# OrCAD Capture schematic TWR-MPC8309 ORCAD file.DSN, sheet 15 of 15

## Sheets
15 P12:CF, 1588, JTAG & I2C Device: size C; title: ColdFire MCU, IEEE1588, JTAG and I2C Device
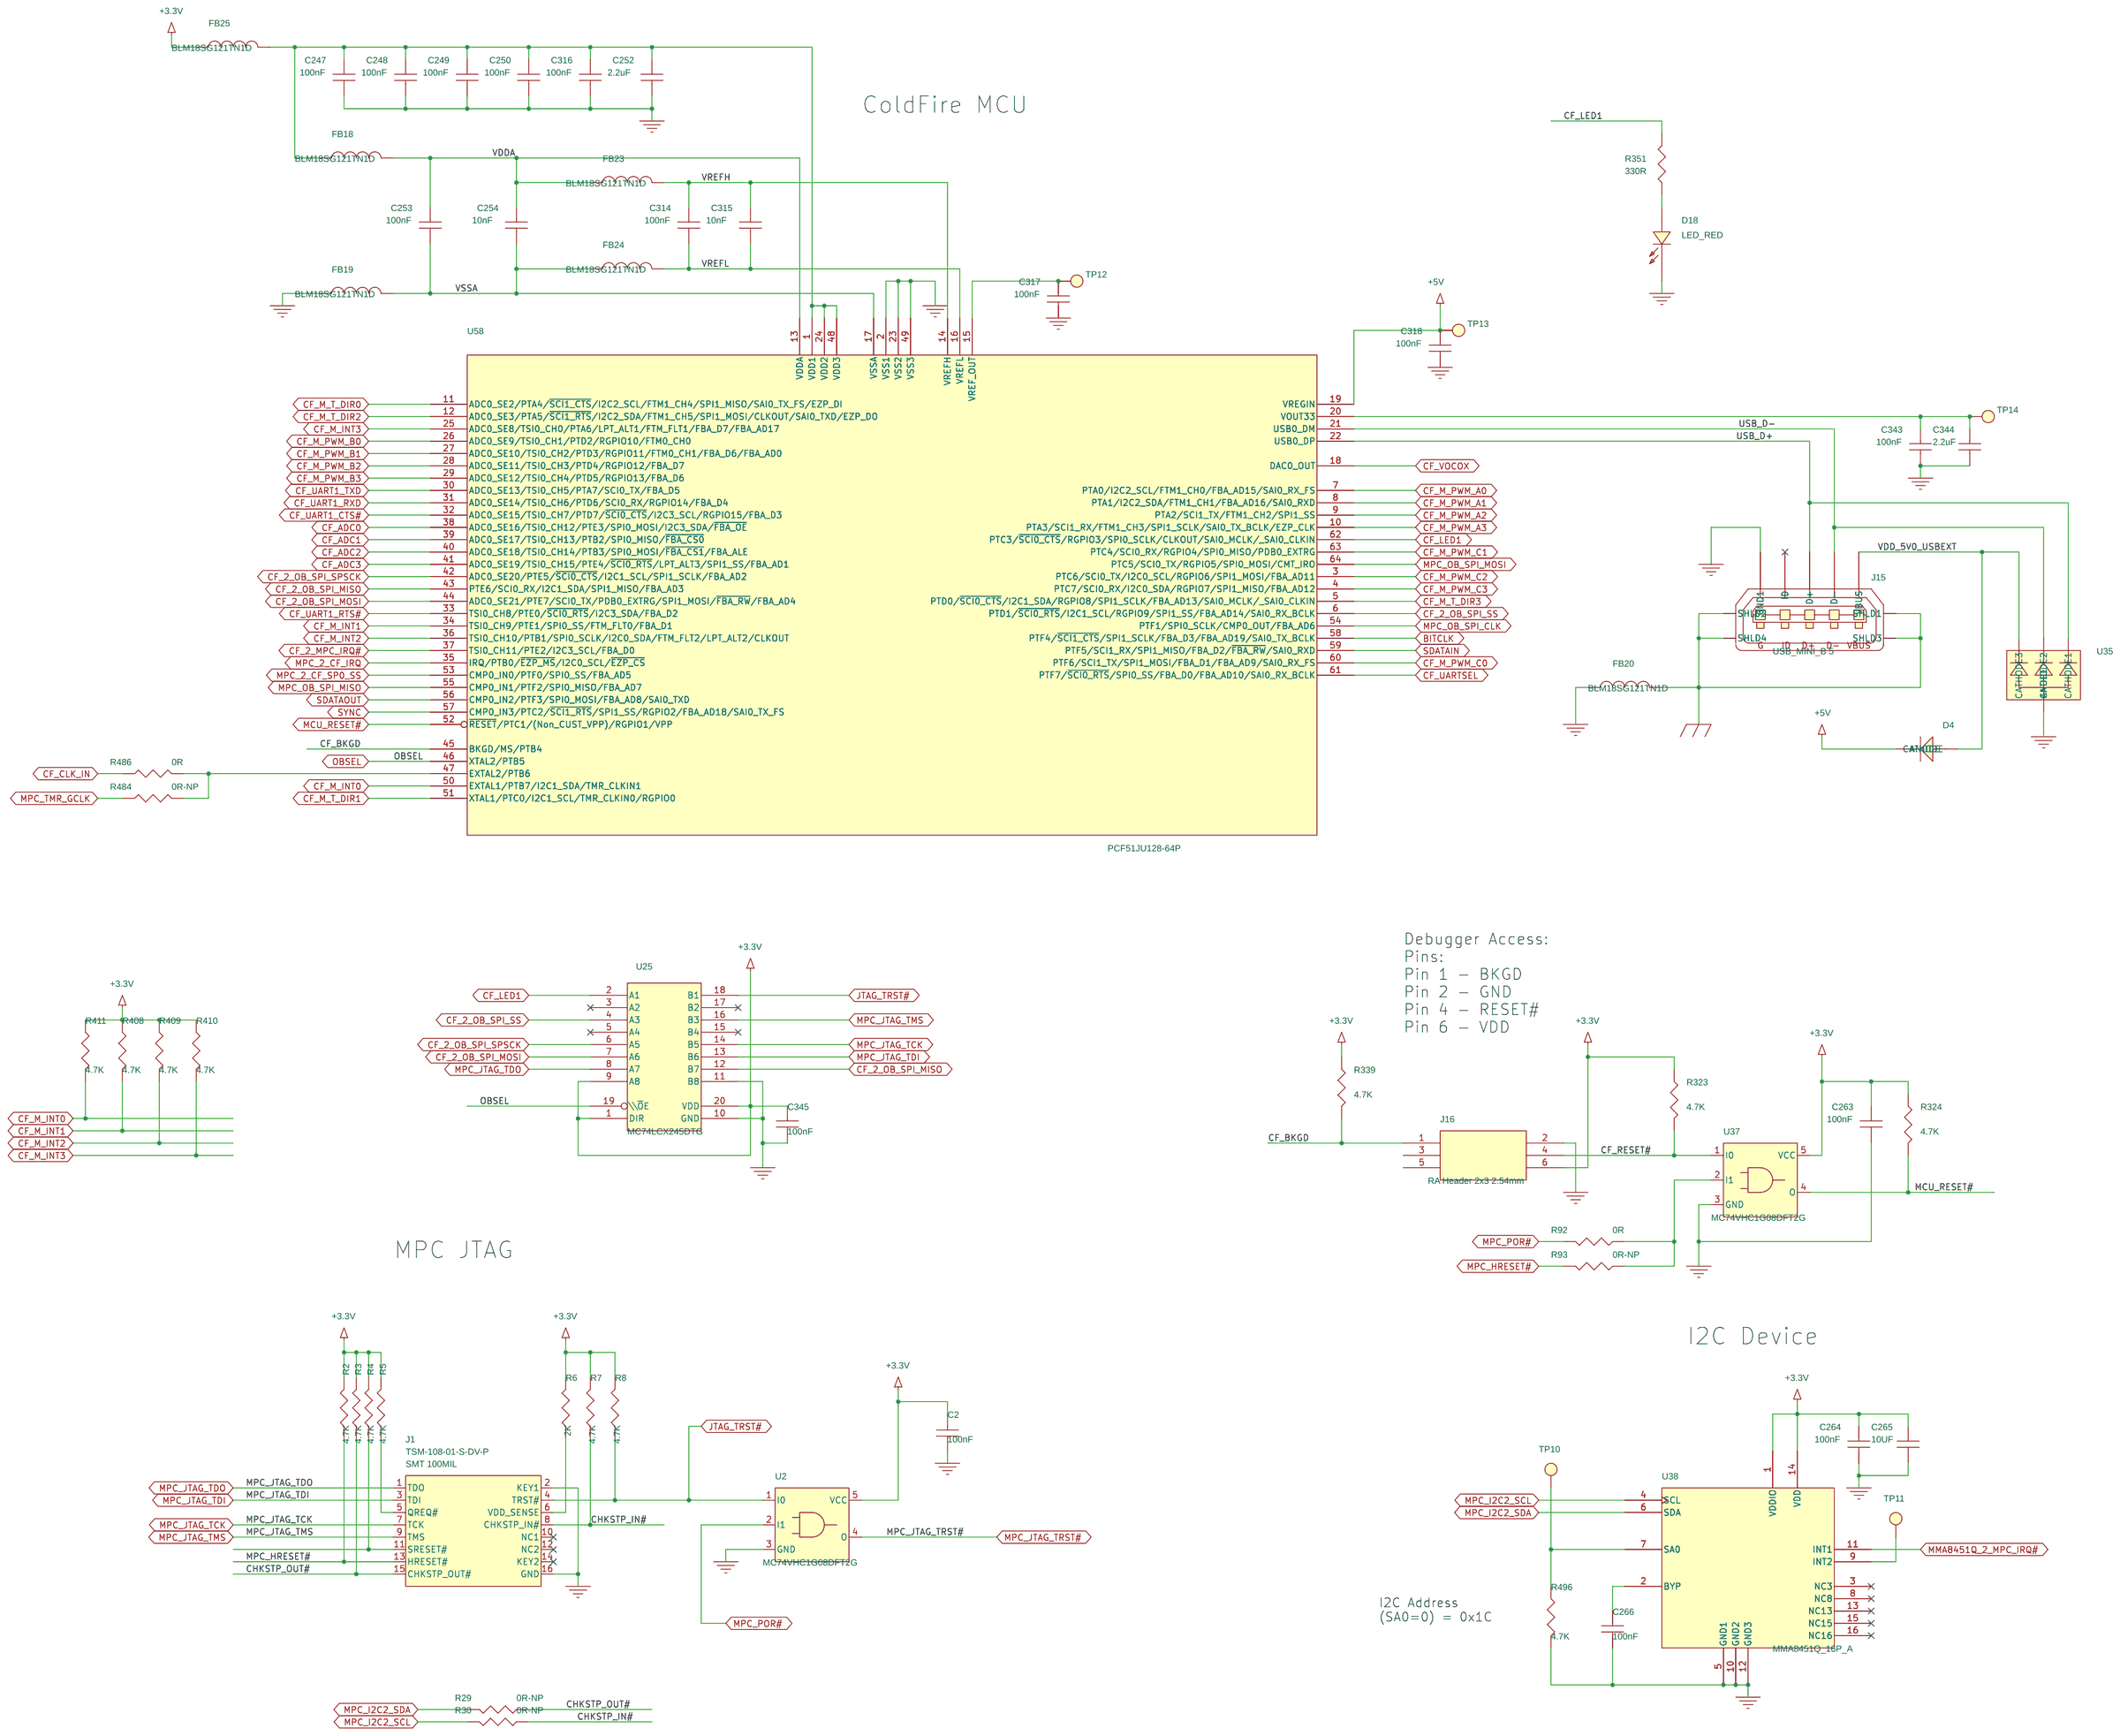
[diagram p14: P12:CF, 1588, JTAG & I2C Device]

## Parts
C2  100nF  [CC0402_CR]
C247  100nF  [CC0402_CR]
C248  100nF  [CC0402_CR]
C249  100nF  [CC0402_CR]
C250  100nF  [CC0402_CR]
C252  2.2uF  [CC0603]
C253  100nF  [CC0402_CR]
C254  10nF  [CC0402_CR]
C263  100nF  [CC0402_CR]
C264  100nF  [CC0402_CR]
C265  10UF  [CC0805]
C266  100nF  [CC0402_CR]
C314  100nF  [CC0402_CR]
C315  10nF  [CC0402_CR]
C316  100nF  [CC0402_CR]
C317  100nF  [CC0402_CR]
C318  100nF  [CC0402_CR]
C343  100nF  [CC0402_CR]
C344  2.2uF  [CC0603]
C345  100nF  [CC0402_CR]
D4  RB060M_30  [SOD_123]
D18  LED_RED  [LED0603]
FB18  BLM18SG121TN1D  [L0603]
FB19  BLM18SG121TN1D  [L0603]
FB20  BLM18SG121TN1D  [L0603]
FB23  BLM18SG121TN1D  [L0603]
FB24  BLM18SG121TN1D  [L0603]
FB25  BLM18SG121TN1D  [L0603]
J1  TSM-108-01-S-DV-P  [Header100_SMD2X8]
J15  USB_MINI_B 5  [CON5_MUSB_ABC_0P8_RA_SMT]
J16  RA Header 2x3 2.54mm  [header100_smd2x3_ra]
R2  4.7K  [R0402_CR]
R3  4.7K  [R0402_CR]
R4  4.7K  [R0402_CR]
R5  4.7K  [R0402_CR]
R6  2K  [R0402_CR]
R7  4.7K  [R0402_CR]
R8  4.7K  [R0402_CR]
R29  0R-NP  [R0402_CR]
R30  0R-NP  [R0402_CR]
R92  0R  [R0402_CR]
R93  0R-NP  [R0402_CR]
R323  4.7K  [R0402_CR]
R324  4.7K  [R0402_CR]
R339  4.7K  [R0402_CR]
R351  330R  [R0402_CR]
R408  4.7K  [R0402_CR]
R409  4.7K  [R0402_CR]
R410  4.7K  [R0402_CR]
R411  4.7K  [R0402_CR]
R484  0R-NP  [R0402_CR]
R486  0R  [R0402_CR]
R496  4.7K  [R0402_CR]
TP10  TP  [SMD_TP]
TP11  TP  [SMD_TP]
TP12  TP  [SMD_TP]
TP13  TP  [SMD_TP]
TP14  TP  [SMD_TP]
U2  MC74VHC1G08DFT2G  [SOT353]
U25  MC74LCX245DTG  [TSSOP20A]
U35  SP0503B  [sot143]
U37  MC74VHC1G08DFT2G  [SOT353]
U38  MMA8451Q_16P_A  [qfn16_0p5_3p03x3p03]
U58  PCF51JU128-64P  [LQFP64_0P5_10x10]

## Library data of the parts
C2 = CAP_NP: Mfg: Kemet; Mfg Part#: C0402C104K8PACTU; Oper. Temp. Range: -55°C ~ 85°C; Package: 0402; Price @ 100 pcs: 0.014; Price @ 10K: 0.0060; Price @ 1K: 0.0066; RoHS Compliant?: Yes; Specifications: CAP .10UF 10V CERAMIC X5R 0402; Vendor: Digikey; Vendor Part#: 399-3027-1-ND
C247-C250 C252-C254 C263 C264 C266 C314-C318 C343 C345 = CAP_NP: CAP CER 0.1UF 16V 10% X7R 0402; AGILE_PN: 150-75182; CAD_APPROVED: Yes; FPLIST: CC0402_25,CC0402_HD,0402_CC; HEIGHT: 0.635MM; MFG_NAME01: MURATA; MFG_PN01: GRM155R71C104KA88D; ROHS: Yes; ROOM: OSBDM; Tolerance: 10%
C265 C344 = CAP_NP: CAP CER 10UF 6.3V 10% X5R 0603; AGILE_PN: 150-77832; CAD_APPROVED: Yes; FPLIST: CC0603_OV,CC0603,0603_CC; HEIGHT: 1.0MM; MFG_NAME01: CAL-CHIP; MFG_PN01: GMC10X5R106K6R3NTLF; ROHS: Yes; ROOM: OSBDM; Tolerance: 10%
D4 = DIODE_0: DIODE PWR RECT 2A 600V 403A-03; AGILE_PN: 480-77641; CAD_APPROVED: Yes; HEIGHT: 2.45MM; MFG_NAME01: ON SEMICONDUCTOR; MFG_PN01: MURS060T3G; ROHS: Yes; ROOM: POWER
D18 = LED: Mfg: Lumex; Mfg Part#: SML-LX0603GW-TR; Package: 0603; RoHS Compliant?: Yes; Specifications: LED 565NM GRN DIFF 0603 SMD
FB18 FB19 FB23-FB25 = INDUCTOR_0: Ferrite Bead, 2A, 140 OHMS, 1GHZ, SMD0603; Cost_Proto: 0.25; Cost_Vol: 0.14; Mfg: Murata; Mfg Part No: BLM18EG101TN1; Room: OSBDM
FB20 = Bead: Ferrite Bead, 6000mA, 0.007E, SMD, 0603; Mfg: Murata; Mfg Part No: BLM18SG260TN1D; Part Number: GBX-R-00000033; ROOM: USB
J1 = CONN_16Pin_2x8_MPC_JTAG: Mfg: Samtec; Oper. Temp. Range: -40°C ~ 105°C; Package: SMT 100MIL; Price @ 100 pcs: 1.4; Price @ 10K: 0.918; Price @ 1K: 1.19; RoHS Compliant?: Yes; Specifications: HDR 2X8 SMT PLUG 100MIL SP 380H AU; Vendor: Samtec
J15 = USB_MINI_B_SKT: CON 1X5 USB MINI-B RA SHLD SKT SMT 0.8MM SP 159H AU; AGILE_PN: 211-78723; CAD_APPROVED: Yes; HEIGHT: 4.05MM; MFG_NAME01: WIN WIN PRECISION INDUSTRIAL CO. LTD; MFG_PN01: MUBF-5S-TSROBTC; ROHS: Yes; ROOM: OSBDM
J16 = Conn_BDC_2x3_male_Header_0: Mfg: Samtec; Mfg Part#: TSM-103-01-L-DV; Package: SMD 100mil; Price @ 100 pcs: 0.324; Price @ 10K: 0.268; Price @ 1K: 0.324; RoHS Compliant?: Yes; Specifications: Conn Header 100mil x 100mil SMD; Vendor: Samtec; Vendor Part#: TSM-103-01-L-DV
R2-R5 = RESISTOR: Mfg: Yageo; Mfg Part#: RC0402JR-075K1L; Oper. Temp. Range: -55°C ~ 85°C; Package: 0402; Price @ 100 pcs: 0.066; Price @ 10K: 0.002; Price @ 1K: 0.035; RoHS Compliant?: Yes; Specifications: RES 5.1K OHM 1/16W 5% 0402 SMD; Vendor: Digikey; Vendor Part#: 311-5.1KJRCT-ND
R6 = RESISTOR: Mfg: Yageo; Mfg Part#: RC0402JR-072KL; Oper. Temp. Range: -55°C ~ 85°C; Package: 0402; Price @ 100 pcs: 0.035; Price @ 10K: 0.002; Price @ 1K: 0.0138; RoHS Compliant?: Yes; Specifications: RES 2.0K OHM 1/16W 5% 0402 SMD; Vendor: Digikey; Vendor Part#: RC0402JR-072KL
R7 R29 R30 R92 R93 = RESISTOR: Mfg: Yageo; Mfg Part#: RC0402JR-074K7L; Oper. Temp. Range: -55°C ~ 85°C; Package: 0402; Price @ 100 pcs: 0.0066; Price @ 10K: 0.00213; Price @ 1K: 0.035; RoHS Compliant?: Yes; Specifications: RES 4.7K OHM 1/16W 5% 0402 SMD; Vendor: Digikey; Vendor Part#: 311-4.7KJRCT-ND
R8 = RESISTOR: Mfg: Yageo; Mfg Part#: RC0402JR-0710KL; Oper. Temp. Range: -55°C ~ 85°C; Package: 0402; Price @ 100 pcs: 0.066; Price @ 10K: 0.00213; Price @ 1K: 0.035; RoHS Compliant?: Yes; Specifications: RES 10K OHM 1/16W 5% 0402 SMD; Vendor: Digikey; Vendor Part#: 311-10KJRCT-ND
R323 R324 R339 R408-R411 R496 = Res: Res, 4.7K, 5%, Chip, 0.063W, SMD, Size 0402; GDA Part No: GRX-R-00000587; Mfg: KOA; Mfg Part No: RK73B1ETTP472J; Part Number: GRX-R-00000587; ROOM: OSBDM; Sub_Type: Chip; Tolerance: 5%
R351 = Res: Res, 100K, 1%, Chip, 0.063W, SMD, Size 0402; FPLIST: R0402; GDA Part No: GRX-R-00000037; Mfg: KOA; Mfg Part No: RK73H1ETTP1003F; Part Number: GRX-R-00000037; ROOM: POWER; Sub_Type: Chip; Tolerance: 1%
R484 R486 = RESISTOR: Mfg: Yageo; Mfg Part#: RC0402FR-0722RL; Package: 0402; Price @ 100 pcs: 0.066; Price @ 10K: 0.036; Price @ 1K: 0.00243; RoHS Compliant?: Yes; Specifications: RES 22.0 OHM 1/16W 1% 0402 SMD; Vendor: Digikey; Vendor Part#: 311-22.0LRCT-ND
TP10 TP11 = TP: RoHS Compliant?: Yes
TP12-TP14 = TP
U2 U37 = 74VHC1G08: IC GATE AND SGL 2-INPUT 2-5.5V SOT-353; AGILE_PN: 312-79604; CAD_APPROVED: Yes; CLASS: IC; HEIGHT: 1.1MM; MFG_NAME01: ON SEMICONDUCTOR; MFG_PN01: MC74VHC1G08DFT1G; ROHS: Yes
U25 = 74LCX245: CLASS: IC
U35 = SPB0503: DIODE TVS ARRAY 3CH -- 5V 0.225W SOT143; AGILE_PN: 480-76886; CAD_APPROVED: Yes; HEIGHT: 1.22MM; MFG_NAME01: LITTELFUSE; MFG_PN01: SP0503BAHTG; ROHS: Yes; ROOM: OSBDM
U38 = MMA8451Q_16P_A
U58 = PCF51JU128-64P

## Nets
+3.3V: C2.2 C263.1 C264.1 C265.1 C345.1 FB25.2 J16.6 R2.2 R3.2 R4.2 R5.2 R6.2 R7.2 R8.2 R323.2 R324.2 R339.2 R408.2 R409.2 R410.2 R411.2 U2.5(VCC) U25.1(DIR) U25.9(A8) U25.20(VDD) U37.5(VCC) U38.1(VDDIO) U38.14(VDD) ; also on sheet 1 2 4 5 7 8 9 10 11 12 13 14
+5V: C318.1 D4.2(ANODE) TP13.1(TP) U58.19(VREGIN) ; also on sheet 1 5 9 11 12
GND: C2.1 C247.2 C248.2 C249.2 C250.2 C252.2 C263.2 C264.2 C265.2 C266.2 C316.2 C317.2 C318.2 C343.2 C344.2 C345.2 D18.2(CATHODE) FB19.2 FB20.2 J1.2(KEY1) J1.16(GND) J15.5(GND1) J16.2 R496.1 U2.3(GND) U25.10(GND) U25.11(B8) U35.1(ANODE) U37.3(GND) U38.5(GND1) U38.10(GND2) U38.12(GND3) U58.2(VSS1) U58.23(VSS2) U58.49(VSS3) ; also on sheet 1 2 4 5 6 7 8 9 10 11 12 13 14
GND_EARTH1: FB20.1 J15.S1(SHLD1) J15.S2(SHLD2) J15.S3(SHLD3) J15.S4(SHLD4)
VDD_5V0_USBEXT: D4.1(CATHODE) J15.1(VBUS) U35.4(CATHODE3)
VDDA: C253.1 C254.1 FB18.1 FB23.2 U58.13(VDDA)
VSSA: C253.2 C254.2 FB19.1 FB24.2 U58.17(VSSA)
BITCLK: U58.58(PTF4/~{SCI1_CTS}/SPI1_SCLK/FBA_D3/FBA_AD19/SAI0_TX_BCLK) ; also on sheet 2
CF_2_MPC_IRQ#: U58.37(TSI0_CH11/PTE2/I2C3_SCL/FBA_D0) ; also on sheet 13
CF_2_OB_SPI_MISO: U25.12(B7) U58.43(PTE6/SCI0_RX/I2C1_SDA/SPI1_MISO/FBA_AD3) ; also on sheet 6
CF_2_OB_SPI_MOSI: U25.7(A6) U58.44(ADC0_SE21/PTE7/SCI0_TX/PDB0_EXTRG/SPI1_MOSI/~{FBA_RW}/FBA_AD4) ; also on sheet 6
CF_2_OB_SPI_SPSCK: U25.6(A5) U58.42(ADC0_SE20/PTE5/~{SCI0_CTS}/I2C1_SCL/SPI1_SCLK/FBA_AD2) ; also on sheet 6
CF_2_OB_SPI_SS: U25.4(A3) U58.6(PTD1/~{SCI0_RTS}/I2C1_SCL/RGPIO9/SPI1_SS/FBA_AD14/SAI0_RX_BCLK) ; also on sheet 6
CF_ADC0: U58.38(ADC0_SE16/TSI0_CH12/PTE3/SPI0_MOSI/I2C3_SDA/~{FBA_OE}) ; also on sheet 5 6
CF_ADC1: U58.39(ADC0_SE17/TSI0_CH13/PTB2/SPI0_MISO/~{FBA_CS0}) ; also on sheet 5 6
CF_ADC2: U58.40(ADC0_SE18/TSI0_CH14/PTB3/SPI0_MOSI/~{FBA_CS1}/FBA_ALE) ; also on sheet 5 6
CF_ADC3: U58.41(ADC0_SE19/TSI0_CH15/PTE4/~{SCI0_RTS}/LPT_ALT3/SPI1_SS/FBA_AD1) ; also on sheet 5 6
CF_BKGD: J16.1 R339.1 U58.45(BKGD/MS/PTB4)
CF_CLK_IN: R486.1 ; also on sheet 8
CF_LED1: R351.2 U25.2(A1) U58.62(PTC3/~{SCI0_CTS}/RGPIO3/SPI0_SCLK/CLKOUT/SAI0_MCLK/_SAI0_CLKIN)
CF_M_INT0: R411.1 U58.50(EXTAL1/PTB7/I2C1_SDA/TMR_CLKIN1) ; also on sheet 6
CF_M_INT1: R408.1 U58.34(TSI0_CH9/PTE1/SPI0_SS/FTM_FLT0/FBA_D1) ; also on sheet 6
CF_M_INT2: R409.1 U58.36(TSI0_CH10/PTB1/SPI0_SCLK/I2C0_SDA/FTM_FLT2/LPT_ALT2/CLKOUT) ; also on sheet 6
CF_M_INT3: R410.1 U58.25(ADC0_SE8/TSI0_CH0/PTA6/LPT_ALT1/FTM_FLT1/FBA_D7/FBA_AD17) ; also on sheet 6
CF_M_PWM_A0: U58.7(PTA0/I2C2_SCL/FTM1_CH0/FBA_AD15/SAI0_RX_FS) ; also on sheet 6
CF_M_PWM_A1: U58.8(PTA1/I2C2_SDA/FTM1_CH1/FBA_AD16/SAI0_RXD) ; also on sheet 6
CF_M_PWM_A2: U58.9(PTA2/SCI1_TX/FTM1_CH2/SPI1_SS) ; also on sheet 6
CF_M_PWM_A3: U58.10(PTA3/SCI1_RX/FTM1_CH3/SPI1_SCLK/SAI0_TX_BCLK/EZP_CLK) ; also on sheet 6
CF_M_PWM_B0: U58.26(ADC0_SE9/TSI0_CH1/PTD2/RGPIO10/FTM0_CH0) ; also on sheet 6
CF_M_PWM_B1: U58.27(ADC0_SE10/TSI0_CH2/PTD3/RGPIO11/FTM0_CH1/FBA_D6/FBA_AD0) ; also on sheet 6
CF_M_PWM_B2: U58.28(ADC0_SE11/TSI0_CH3/PTD4/RGPIO12/FBA_D7) ; also on sheet 6
CF_M_PWM_B3: U58.29(ADC0_SE12/TSI0_CH4/PTD5/RGPIO13/FBA_D6) ; also on sheet 6
CF_M_PWM_C0: U58.60(PTF6/SCI1_TX/SPI1_MOSI/FBA_D1/FBA_AD9/SAI0_RX_FS) ; also on sheet 6
CF_M_PWM_C1: U58.63(PTC4/SCI0_RX/RGPIO4/SPI0_MISO/PDB0_EXTRG) ; also on sheet 6
CF_M_PWM_C2: U58.3(PTC6/SCI0_TX/I2C0_SCL/RGPIO6/SPI1_MOSI/FBA_AD11) ; also on sheet 6
CF_M_PWM_C3: U58.4(PTC7/SCI0_RX/I2C0_SDA/RGPIO7/SPI1_MISO/FBA_AD12) ; also on sheet 6
CF_M_T_DIR0: U58.11(ADC0_SE2/PTA4/~{SCI1_CTS}/I2C2_SCL/FTM1_CH4/SPI1_MISO/SAI0_TX_FS/EZP_DI) ; also on sheet 6
CF_M_T_DIR1: U58.51(XTAL1/PTC0/I2C1_SCL/TMR_CLKIN0/RGPIO0) ; also on sheet 6
CF_M_T_DIR2: U58.12(ADC0_SE3/PTA5/~{SCI1_RTS}/I2C2_SDA/FTM1_CH5/SPI1_MOSI/CLKOUT/SAI0_TXD/EZP_DO) ; also on sheet 6
CF_M_T_DIR3: U58.5(PTD0/~{SCI0_CTS}/I2C1_SDA/RGPIO8/SPI1_SCLK/FBA_AD13/SAI0_MCLK/_SAI0_CLKIN) ; also on sheet 6
CF_RESET#: J16.4 R323.1 U37.1(I0)
CF_UART1_CTS#: U58.32(ADC0_SE15/TSI0_CH7/PTD7/~{SCI0_CTS}/I2C3_SCL/RGPIO15/FBA_D3) ; also on sheet 12
CF_UART1_RTS#: U58.33(TSI0_CH8/PTE0/~{SCI0_RTS}/I2C3_SDA/FBA_D2) ; also on sheet 6 12
CF_UART1_RXD: U58.31(ADC0_SE14/TSI0_CH6/PTD6/SCI0_RX/RGPIO14/FBA_D4) ; also on sheet 12
CF_UART1_TXD: U58.30(ADC0_SE13/TSI0_CH5/PTA7/SCI0_TX/FBA_D5) ; also on sheet 12
CF_UARTSEL: U58.61(PTF7/~{SCI0_RTS}/SPI0_SS/FBA_D0/FBA_AD10/SAI0_RX_BCLK)
CF_VOCOX: U58.18(DAC0_OUT) ; also on sheet 6 8
CHKSTP_IN#: J1.8(CHKSTP_IN#) R7.1 R30.2
CHKSTP_OUT#: J1.15(CHKSTP_OUT#) R3.1 R29.2
JTAG_TRST#: J1.4(TRST#) R8.1 U2.1(I0) U25.18(B1)
MCU_RESET#: R324.1 U37.4(O) U58.52(~{RESET}/PTC1/(Non_CUST_VPP)/RGPIO1/VPP)
MMA8451Q_2_MPC_IRQ#: U38.11(INT1) ; also on sheet 13
MPC_2_CF_IRQ: U58.35(IRQ/PTB0/~{EZP_MS}/I2C0_SCL/~{EZP_CS}) ; also on sheet 13
MPC_2_CF_SP0_SS: U58.53(CMP0_IN0/PTF0/SPI0_SS/FBA_AD5) ; also on sheet 13
MPC_HRESET#: J1.13(HRESET#) R2.1 R93.1 ; also on sheet 5 6 7 8
MPC_I2C2_SCL: R30.1 U38.4(SCL) ; also on sheet 2 5 6 13
MPC_I2C2_SDA: R29.1 U38.6(SDA) ; also on sheet 2 5 6 13
MPC_JTAG_TCK: J1.7(TCK) U25.14(B5) ; also on sheet 8
MPC_JTAG_TDI: J1.3(TDI) U25.13(B6) ; also on sheet 8
MPC_JTAG_TDO: J1.1(TDO) U25.8(A7) ; also on sheet 8
MPC_JTAG_TMS: J1.9(TMS) U25.16(B3) ; also on sheet 8
MPC_JTAG_TRST#: U2.4(O) ; also on sheet 8
MPC_OB_SPI_CLK: U58.54(PTF1/SPI0_SCLK/CMP0_OUT/FBA_AD6) ; also on sheet 5 6 13
MPC_OB_SPI_MISO: U58.55(CMP0_IN1/PTF2/SPI0_MISO/FBA_AD7) ; also on sheet 5 6 13
MPC_OB_SPI_MOSI: U58.64(PTC5/SCI0_TX/RGPIO5/SPI0_MOSI/CMT_IRO) ; also on sheet 5 6 13
MPC_POR#: R92.1 U2.2(I1) ; also on sheet 8 10
MPC_TMR_GCLK: R484.1 ; also on sheet 2 14
OBSEL: U25.19(\\~{O}E) U58.46(XTAL2/PTB5) ; also on sheet 13
SDATAIN: U58.59(PTF5/SCI1_RX/SPI1_MISO/FBA_D2/~{FBA_RW}/SAI0_RXD) ; also on sheet 2
SDATAOUT: U58.56(CMP0_IN2/PTF3/SPI0_MOSI/FBA_AD8/SAI0_TXD) ; also on sheet 2
SYNC: U58.57(CMP0_IN3/PTC2/~{SCI1_RTS}/SPI1_SS/RGPIO2/FBA_AD18/SAI0_TX_FS) ; also on sheet 2
USB_D+: J15.3(D+) U35.2(CATHODE1) U58.22(USB0_DP)
USB_D-: J15.2(D-) U35.3(CATHODE2) U58.21(USB0_DM)
VREFH: C314.1 C315.1 FB23.1 U58.14(VREFH)
VREFL: C314.2 C315.2 FB24.1 U58.16(VREFL)
N21032931: C247.1 C248.1 C249.1 C250.1 C252.1 C316.1 FB18.2 FB25.1 U58.1(VDD1) U58.24(VDD2) U58.48(VDD3)
N24389672: C266.1 U38.2(BYP)
N24413802: TP11.1(TP) U38.9(INT2)
N24757302: R92.2 R93.2 U37.2(I1)
N30559249: C343.1 C344.1 TP14.1(TP) U58.20(VOUT33)
N30975642: D18.1(ANODE) R351.1
N31943754: C317.1 TP12.1(TP) U58.15(VREF_OUT)
N39615956: R484.2 R486.2 U58.47(EXTAL2/PTB6)
N42137337: J1.11(SRESET#) R4.1
N42137357: J1.6(VDD_SENSE) R6.1
N42137416: J1.5(QREQ#) R5.1
N42948376: R496.2 TP10.1(TP) U38.7(SA0)

Not connected (* = marked no-connect by the designer): J1 10(NC1)* 12(NC2)* 14(KEY2)*; J15 4(ID)*; J16 3 5; U25 3(A2)* 5(A4)* 15(B4)* 17(B2)*; U38 3(NC3)* 8(NC8)* 13(NC13)* 15(NC15)* 16(NC16)*

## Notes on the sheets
sheet 15
- ColdFire MCU
- Debugger Access:
  Pins:
  Pin 1 - BKGD
  Pin 2 - GND
  Pin 4 - RESET#
  Pin 6 - VDD
- MPC JTAG
- I2C Device
- I2C Address
  (SA0=0) = 0x1C
